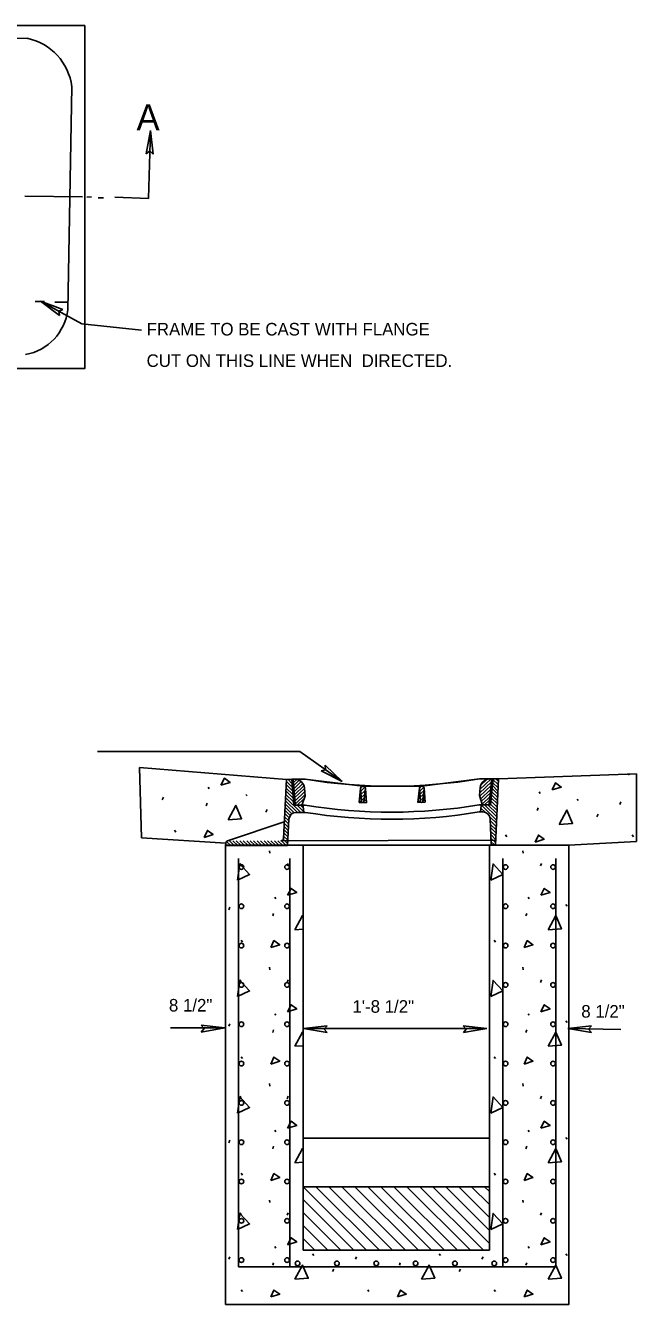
# Model space of a CAD drawing. Extents: x 0.9 to 8.1, y 0.4 to 10.5.
# Drawn here: x 5.569 to 7.899, y 5.354 to 10.233 of the extents above; entities that cross this region are included whole.
import ezdxf

# ---------------------------------------------------------------- set-up
doc = ezdxf.new("R2010")
doc.units = 0
for name, color, linetype in [('DETL-DIMS', 7, 'Continuous'), ('DETL-LINE', 7, 'Continuous'), ('DETL-NOTE', 7, 'Continuous')]:
    doc.layers.add(name, color=color, linetype=linetype)

msp = doc.modelspace()

# ---------------------------------------------------------------- linework, layer by layer
at = {"layer": 'DETL-DIMS'}
for p, q in [((6.0293, 9.7442), (6.0452, 9.8337)), ((6.0372, 9.5743), (6.0452, 9.8337)), ((6.0556, 9.7433), (6.0452, 9.8337)), ((6.0293, 9.7442), (6.0428, 9.755)), ((6.0556, 9.7433), (6.0428, 9.755)), ((5.9096, 9.5783), (6.0372, 9.5743)), ((5.6988, 9.1267), (5.6262, 9.1815)), ((5.7114, 9.1497), (5.6262, 9.1815)), ((5.7114, 9.1497), (5.6952, 9.1436)), ((5.6988, 9.1267), (5.6952, 9.1436)), ((6.696, 7.3899), (6.7127, 7.3941)), ((6.696, 7.3899), (6.777, 7.3486)), ((6.7111, 7.4113), (6.777, 7.3486)), ((6.7111, 7.4113), (6.7127, 7.3941)), ((6.1222, 6.4089), (6.3284, 6.4089)), ((6.238, 6.4192), (6.3284, 6.4089)), ((6.238, 6.4192), (6.2497, 6.4065)), ((6.2389, 6.393), (6.3284, 6.4089)), ((6.2389, 6.393), (6.2497, 6.4065)), ((6.7199, 6.4172), (6.6295, 6.4068)), ((6.6295, 6.4068), (7.3286, 6.4068)), ((6.7191, 6.3909), (6.6295, 6.4068)), ((6.7199, 6.4172), (6.7082, 6.4044)), ((6.7191, 6.3909), (6.7082, 6.4044)), ((7.2382, 6.4172), (7.3286, 6.4068)), ((7.2382, 6.4172), (7.2499, 6.4044)), ((7.2391, 6.3909), (7.3286, 6.4068)), ((7.2391, 6.3909), (7.2499, 6.4044)), ((7.7283, 6.4172), (7.6379, 6.4068)), ((7.6379, 6.4068), (7.84, 6.4027)), ((7.7275, 6.3909), (7.6379, 6.4068)), ((7.7283, 6.4172), (7.7167, 6.4044)), ((7.7275, 6.3909), (7.7167, 6.4044))]:
    msp.add_line(p, q, dxfattribs=at)
for points in [[(5.6262, 9.1815), (5.783, 9.0954), (6.0106, 9.0707)], [(6.777, 7.3486), (6.6151, 7.4633), (5.8426, 7.4642)]]:
    msp.add_lwpolyline(points, dxfattribs=at)
at = {"layer": 'DETL-LINE'}
for p, q in [((3.772, 10.1935), (5.5744, 10.1848)), ((5.7451, 10.0004), (5.7302, 9.1491)), ((5.6058, 9.1805), (5.6407, 9.1805)), ((5.6801, 9.1782), (5.7285, 9.1782)), ((6.5636, 7.3574), (6.0035, 7.4026)), ((6.0035, 7.4026), (6.0106, 7.1346)), ((7.3732, 7.3593), (7.8991, 7.3779)), ((7.873, 7.3769), (7.8693, 7.3752)), ((7.8693, 7.3752), (7.8695, 7.3768)), ((7.8991, 7.1205), (7.8991, 7.3779)), ((6.2658, 7.3277), (6.2694, 7.3217)), ((6.5527, 7.1319), (6.5636, 7.3574)), ((6.5621, 7.3253), (6.5894, 7.2988)), ((6.5627, 7.3376), (6.5883, 7.3128)), ((6.5633, 7.3499), (6.5871, 7.3267)), ((6.5636, 7.3574), (6.5847, 7.3575)), ((6.5688, 7.3575), (6.586, 7.3407)), ((6.582, 7.3575), (6.5849, 7.3546)), ((6.5847, 7.3575), (6.5926, 7.2584)), ((6.5847, 7.3575), (6.5894, 7.3575)), ((6.5894, 7.3575), (6.5969, 7.2625)), ((6.5894, 7.3575), (6.5961, 7.3575)), ((6.5895, 7.3566), (6.5904, 7.3575)), ((6.5904, 7.3448), (6.603, 7.3569)), ((6.5913, 7.3331), (6.6129, 7.3537)), ((6.5922, 7.3214), (6.6207, 7.3486)), ((6.5932, 7.3097), (6.6269, 7.3418)), ((6.5941, 7.298), (6.6312, 7.3334)), ((6.595, 7.2863), (6.6332, 7.3227)), ((6.5961, 7.3575), (6.6338, 7.3576)), ((6.633, 7.3247), (6.6354, 7.294)), ((6.8558, 7.3311), (6.6338, 7.3576)), ((6.8411, 7.2692), (6.8464, 7.3228)), ((6.8451, 7.3094), (6.8635, 7.3271)), ((6.8505, 7.2727), (6.8464, 7.3228)), ((6.8465, 7.3234), (6.8544, 7.331)), ((6.9681, 7.3313), (6.8558, 7.3311)), ((6.8598, 7.2728), (6.865, 7.3228)), ((6.8691, 7.268), (6.865, 7.3228)), ((6.9681, 7.3313), (7.0804, 7.3316)), ((7.0657, 7.2685), (7.071, 7.3233)), ((7.0697, 7.3096), (7.0883, 7.3274)), ((7.071, 7.3235), (7.0795, 7.3315)), ((7.0751, 7.2732), (7.071, 7.3233)), ((7.0804, 7.3316), (7.3007, 7.3591)), ((7.0844, 7.2732), (7.0897, 7.3233)), ((7.0938, 7.2697), (7.0897, 7.3233)), ((7.3031, 7.3262), (7.2999, 7.2955)), ((7.3408, 7.3592), (7.3007, 7.3591)), ((7.3009, 7.3046), (7.3463, 7.348)), ((7.301, 7.2921), (7.3449, 7.334)), ((7.3023, 7.3186), (7.3449, 7.3592)), ((7.304, 7.2824), (7.3435, 7.32)), ((7.3046, 7.3333), (7.3301, 7.3577)), ((7.3475, 7.3592), (7.3377, 7.2642)), ((7.3475, 7.3592), (7.3408, 7.3592)), ((7.3522, 7.3592), (7.342, 7.2601)), ((7.3522, 7.3592), (7.3475, 7.3592)), ((7.3483, 7.3219), (7.3704, 7.3005)), ((7.3495, 7.3336), (7.371, 7.3128)), ((7.3507, 7.3453), (7.3715, 7.3251)), ((7.3519, 7.357), (7.3721, 7.3374)), ((7.3732, 7.3593), (7.3522, 7.3592)), ((7.3732, 7.3593), (7.3609, 7.1057)), ((7.3629, 7.3592), (7.3727, 7.3497)), ((6.0895, 7.2794), (6.0943, 7.2891)), ((6.4095, 7.2999), (6.4144, 7.2939)), ((6.5597, 7.2761), (6.6057, 7.2314)), ((6.5603, 7.2884), (6.6189, 7.2314)), ((6.5609, 7.3007), (6.5916, 7.2709)), ((6.5615, 7.313), (6.5905, 7.2848)), ((6.596, 7.2746), (6.6341, 7.311)), ((6.5969, 7.2629), (6.635, 7.2992)), ((6.6055, 7.2584), (6.632, 7.2838)), ((6.6245, 7.2614), (6.6354, 7.294)), ((6.8423, 7.2816), (6.8664, 7.3046)), ((6.8424, 7.2691), (6.8673, 7.2928)), ((6.8437, 7.2955), (6.8655, 7.3164)), ((6.8551, 7.2686), (6.8681, 7.2811)), ((7.0663, 7.2685), (7.092, 7.293)), ((7.067, 7.2818), (7.0911, 7.3048)), ((7.0683, 7.2957), (7.0902, 7.3165)), ((7.0801, 7.2691), (7.0929, 7.2813)), ((7.3101, 7.2629), (7.2999, 7.2955)), ((7.3071, 7.2727), (7.342, 7.3061)), ((7.3101, 7.263), (7.3406, 7.2921)), ((7.3202, 7.26), (7.3392, 7.2781)), ((7.3435, 7.275), (7.368, 7.2513)), ((7.3447, 7.2867), (7.3686, 7.2636)), ((7.3459, 7.2984), (7.3692, 7.2759)), ((7.3471, 7.3102), (7.3698, 7.2882)), ((7.5287, 7.31), (7.5324, 7.304)), ((7.6725, 7.2822), (7.6773, 7.2762)), ((7.8355, 7.2617), (7.8403, 7.2714)), ((6.2574, 7.2565), (6.261, 7.2661)), ((6.4856, 7.2323), (6.4904, 7.242)), ((6.5573, 7.2269), (6.5745, 7.2102)), ((6.5579, 7.2392), (6.5785, 7.2192)), ((6.5585, 7.2515), (6.5849, 7.2258)), ((6.5591, 7.2638), (6.5938, 7.2301)), ((6.5926, 7.2584), (6.6235, 7.2585)), ((6.6015, 7.2584), (6.6201, 7.2585)), ((6.602, 7.2314), (6.6238, 7.2314)), ((6.6044, 7.2584), (6.6298, 7.2338)), ((6.6176, 7.2585), (6.6287, 7.2478)), ((6.6187, 7.2585), (6.6258, 7.2652)), ((6.6235, 7.2585), (6.6264, 7.2585)), ((6.6235, 7.2585), (6.635, 7.2585)), ((6.6238, 7.2314), (6.63, 7.2315)), ((6.6281, 7.2544), (6.63, 7.2315)), ((6.63, 7.2315), (6.6347, 7.2315)), ((6.8411, 7.2692), (6.8691, 7.268)), ((6.8678, 7.2681), (6.869, 7.2693)), ((7.0938, 7.2697), (7.0657, 7.2685)), ((7.304, 7.233), (7.2992, 7.233)), ((7.311, 7.26), (7.2995, 7.26)), ((7.3063, 7.2559), (7.304, 7.233)), ((7.3101, 7.233), (7.304, 7.233)), ((7.3043, 7.2358), (7.3072, 7.233)), ((7.3055, 7.2475), (7.3218, 7.2317)), ((7.3075, 7.2584), (7.3656, 7.2021)), ((7.311, 7.26), (7.3081, 7.26)), ((7.3132, 7.233), (7.3101, 7.233)), ((7.342, 7.2601), (7.311, 7.26)), ((7.333, 7.2601), (7.3145, 7.26)), ((7.3191, 7.26), (7.3662, 7.2144)), ((7.3324, 7.2601), (7.3668, 7.2267)), ((7.3335, 7.2601), (7.3377, 7.2642)), ((7.3423, 7.2633), (7.3674, 7.239)), ((7.5203, 7.2387), (7.5239, 7.2484)), ((7.7486, 7.2146), (7.7534, 7.2243)), ((6.5558, 7.1955), (6.3388, 7.1222)), ((6.5549, 7.1777), (6.5711, 7.1619)), ((6.5555, 7.19), (6.5718, 7.1741)), ((6.5561, 7.2023), (6.5726, 7.1863)), ((6.5567, 7.2146), (6.5733, 7.1985)), ((6.5678, 7.1052), (6.5737, 7.2055)), ((7.3396, 7.2144), (7.365, 7.1898)), ((7.3446, 7.1069), (7.341, 7.2073)), ((7.3412, 7.1999), (7.3644, 7.1775)), ((7.3417, 7.1866), (7.3638, 7.1652)), ((7.3422, 7.1732), (7.3632, 7.1528)), ((6.3323, 7.1134), (6.0106, 7.1346)), ((6.1366, 7.1635), (6.1414, 7.1562)), ((7.3615, 7.125), (6.5432, 7.1232)), ((6.552, 7.129), (6.5682, 7.1132)), ((6.5531, 7.1408), (6.569, 7.1254)), ((6.5537, 7.1531), (6.5697, 7.1376)), ((6.5543, 7.1654), (6.5704, 7.1497)), ((7.3427, 7.1599), (7.3626, 7.1405)), ((7.3431, 7.1465), (7.362, 7.1282)), ((7.3436, 7.1332), (7.3614, 7.1159)), ((7.3995, 7.1458), (7.4044, 7.1385)), ((7.8826, 7.1458), (7.8874, 7.1385)), ((6.3314, 7.1047), (6.3324, 7.1145)), ((6.5678, 7.1052), (6.3314, 7.1047)), ((6.3321, 7.1106), (6.3382, 7.1047)), ((6.3355, 7.1202), (6.3514, 7.1047)), ((6.3462, 7.1227), (6.3647, 7.1047)), ((6.3594, 7.1227), (6.3779, 7.1048)), ((6.3726, 7.1228), (6.3911, 7.1048)), ((6.3859, 7.1228), (6.4044, 7.1048)), ((6.3991, 7.1228), (6.4176, 7.1049)), ((6.4123, 7.1229), (6.4309, 7.1049)), ((6.4256, 7.1229), (6.4441, 7.1049)), ((6.4388, 7.1229), (6.4573, 7.1049)), ((6.452, 7.123), (6.4706, 7.105)), ((6.4653, 7.123), (6.4838, 7.105)), ((6.4785, 7.123), (6.497, 7.105)), ((6.4918, 7.123), (6.5103, 7.1051)), ((6.4995, 7.0852), (6.5007, 7.0756)), ((6.505, 7.1231), (6.5235, 7.1051)), ((6.5182, 7.1231), (6.5367, 7.1051)), ((6.5315, 7.1231), (6.55, 7.1052)), ((6.5445, 7.1233), (6.5632, 7.1052)), ((7.3446, 7.1069), (6.5678, 7.1052)), ((6.6272, 7.1053), (6.6272, 5.5604)), ((7.3389, 7.1057), (7.3389, 5.5604)), ((7.3441, 7.1198), (7.3574, 7.107)), ((7.3609, 7.107), (7.3446, 7.1069)), ((7.4657, 7.0852), (7.4669, 7.0756)), ((7.8991, 7.1205), (7.6419, 7.1057)), ((6.3814, 5.4978), (6.3814, 7.0556)), ((6.3914, 7.0273), (6.3877, 7.0369)), ((6.5672, 7.0273), (6.5708, 7.0369)), ((6.5772, 5.4978), (6.5772, 7.0556)), ((7.3889, 7.0556), (7.3889, 5.4978)), ((7.5333, 7.0273), (7.537, 7.0369)), ((7.5919, 7.0556), (7.5919, 5.4978)), ((6.5201, 6.9077), (6.5237, 6.9017)), ((7.4862, 6.9077), (7.4899, 6.9017)), ((6.3437, 6.8594), (6.3486, 6.8691)), ((6.5116, 6.8364), (6.5152, 6.8461)), ((7.4778, 6.8364), (7.4814, 6.8461)), ((7.6299, 6.8799), (7.6348, 6.8739)), ((6.6272, 6.7855), (6.5961, 6.7833)), ((6.3908, 6.7435), (6.3957, 6.7362)), ((7.357, 6.7435), (7.3618, 6.7362)), ((6.4995, 6.6408), (6.5007, 6.6311)), ((7.4657, 6.6408), (7.4669, 6.6311)), ((6.3914, 6.5828), (6.3877, 6.5925)), ((6.5672, 6.5828), (6.5708, 6.5925)), ((7.5333, 6.5828), (7.537, 6.5925)), ((6.5201, 6.4633), (6.5237, 6.4572)), ((7.4862, 6.4633), (7.4899, 6.4572)), ((6.3437, 6.415), (6.3486, 6.4246)), ((6.5116, 6.392), (6.5152, 6.4017)), ((7.4778, 6.392), (7.4814, 6.4017)), ((7.6299, 6.4355), (7.6348, 6.4294)), ((6.3908, 6.299), (6.3957, 6.2918)), ((6.6272, 6.3411), (6.5961, 6.3389)), ((7.357, 6.299), (7.3618, 6.2918)), ((6.4995, 6.1964), (6.5007, 6.1867)), ((7.4657, 6.1964), (7.4669, 6.1867)), ((6.3914, 6.1384), (6.3877, 6.148)), ((6.5672, 6.1384), (6.5708, 6.148)), ((7.5333, 6.1384), (7.537, 6.148)), ((6.5201, 6.0188), (6.5237, 6.0128)), ((7.4862, 6.0188), (7.4899, 6.0128)), ((6.3437, 5.9705), (6.3486, 5.9802)), ((6.5116, 5.9476), (6.5152, 5.9572)), ((6.6272, 5.9888), (7.3389, 5.9888)), ((7.4778, 5.9476), (7.4814, 5.9572)), ((7.6299, 5.991), (7.6348, 5.985)), ((6.6272, 5.8966), (6.5961, 5.8944)), ((6.3908, 5.8546), (6.3957, 5.8473)), ((7.357, 5.8546), (7.3618, 5.8473)), ((7.3389, 5.8032), (6.6272, 5.8032)), ((6.6272, 5.8032), (6.87, 5.5604)), ((6.6767, 5.8032), (6.9195, 5.5604)), ((6.7262, 5.8032), (6.969, 5.5604)), ((6.7757, 5.8032), (7.0185, 5.5604)), ((6.8251, 5.8032), (7.068, 5.5604)), ((6.8746, 5.8032), (7.1175, 5.5604)), ((6.9241, 5.8032), (7.167, 5.5604)), ((6.9736, 5.8032), (7.2164, 5.5604)), ((7.0231, 5.8032), (7.2659, 5.5604)), ((7.0726, 5.8032), (7.3154, 5.5604)), ((7.1221, 5.8032), (7.3389, 5.5864)), ((7.1716, 5.8032), (7.3389, 5.6359)), ((7.2211, 5.8032), (7.3389, 5.6854)), ((7.2706, 5.8032), (7.3389, 5.7349)), ((7.3201, 5.8032), (7.3389, 5.7844)), ((6.4995, 5.7519), (6.5007, 5.7423)), ((6.6272, 5.7537), (6.8205, 5.5604)), ((7.4657, 5.7519), (7.4669, 5.7423)), ((6.3914, 5.6939), (6.3877, 5.7036)), ((6.5672, 5.6939), (6.5708, 5.7036)), ((6.6272, 5.7042), (6.771, 5.5604)), ((7.5333, 5.6939), (7.537, 5.7036)), ((6.6272, 5.6547), (6.7215, 5.5604)), ((6.5201, 5.5744), (6.5237, 5.5683)), ((6.6272, 5.6052), (6.672, 5.5604)), ((7.4862, 5.5744), (7.4899, 5.5683)), ((6.3437, 5.5261), (6.3486, 5.5357)), ((6.6272, 5.5604), (7.3389, 5.5604)), ((6.6638, 5.5466), (6.6686, 5.5406)), ((6.8268, 5.5261), (6.8316, 5.5357)), ((7.1469, 5.5466), (7.1517, 5.5406)), ((7.3099, 5.5261), (7.3147, 5.5357)), ((7.6299, 5.5466), (7.6348, 5.5406)), ((6.5772, 5.4978), (6.3814, 5.4978)), ((6.5116, 5.5031), (6.5152, 5.5128)), ((7.3889, 5.4978), (6.5772, 5.4978)), ((6.7399, 5.479), (6.7447, 5.4886)), ((6.9947, 5.5031), (6.9983, 5.5128)), ((7.2229, 5.479), (7.2278, 5.4886)), ((7.5919, 5.4978), (7.3889, 5.4978)), ((7.4778, 5.5031), (7.4814, 5.5128)), ((6.3908, 5.4101), (6.3957, 5.4029)), ((6.8739, 5.4101), (6.8787, 5.4029)), ((7.357, 5.4101), (7.3618, 5.4029))]:
    msp.add_line(p, q, dxfattribs=at)
for points in [[(3.5539, 10.2335), (5.7946, 10.2335), (5.7946, 8.9249), (3.5539, 8.9249)], [(6.3314, 5.3539), (7.6419, 5.3539), (7.6419, 7.1057), (6.3314, 7.1057)]]:
    msp.add_lwpolyline(points, close=True, dxfattribs=at)
for points in [[(6.3141, 7.335), (6.3274, 7.3615), (6.3491, 7.3458), (6.3141, 7.335)], [(7.5771, 7.3172), (7.5903, 7.3438), (7.6121, 7.3281), (7.5771, 7.3172)], [(6.3419, 7.2033), (6.3709, 7.2577), (6.3926, 7.2069), (6.3419, 7.2033)], [(7.6048, 7.1856), (7.6338, 7.24), (7.6556, 7.1892), (7.6048, 7.1856)], [(6.2501, 7.1357), (6.2622, 7.1623), (6.2839, 7.1466), (6.2501, 7.1357)], [(7.513, 7.118), (7.5251, 7.1445), (7.5469, 7.1288), (7.513, 7.118)], [(6.3775, 6.9729), (6.386, 7.0345), (6.4234, 6.9947), (6.3775, 6.9729)], [(7.3437, 6.9729), (7.3522, 7.0345), (7.3896, 6.9947), (7.3437, 6.9729)], [(6.5684, 6.915), (6.5816, 6.9415), (6.6034, 6.9258), (6.5684, 6.915)], [(7.5345, 6.915), (7.5478, 6.9415), (7.5696, 6.9258), (7.5345, 6.915)], [(6.5961, 6.7833), (6.6251, 6.8377), (6.6272, 6.8329)], [(7.5623, 6.7833), (7.5913, 6.8377), (7.613, 6.7869), (7.5623, 6.7833)], [(6.5044, 6.7157), (6.5164, 6.7422), (6.5382, 6.7265), (6.5044, 6.7157)], [(7.4705, 6.7157), (7.4826, 6.7422), (7.5043, 6.7265), (7.4705, 6.7157)], [(6.3775, 6.5285), (6.386, 6.5901), (6.4234, 6.5502), (6.3775, 6.5285)], [(7.3437, 6.5285), (7.3522, 6.5901), (7.3896, 6.5502), (7.3437, 6.5285)], [(6.5684, 6.4705), (6.5816, 6.4971), (6.6034, 6.4814), (6.5684, 6.4705)], [(7.5345, 6.4705), (7.5478, 6.4971), (7.5696, 6.4814), (7.5345, 6.4705)], [(6.5961, 6.3389), (6.6251, 6.3932), (6.6272, 6.3885)], [(7.5623, 6.3389), (7.5913, 6.3932), (7.613, 6.3425), (7.5623, 6.3389)], [(6.5044, 6.2712), (6.5164, 6.2978), (6.5382, 6.2821), (6.5044, 6.2712)], [(7.4705, 6.2712), (7.4826, 6.2978), (7.5043, 6.2821), (7.4705, 6.2712)], [(6.3775, 6.084), (6.386, 6.1456), (6.4234, 6.1058), (6.3775, 6.084)], [(7.3437, 6.084), (7.3522, 6.1456), (7.3896, 6.1058), (7.3437, 6.084)], [(6.5684, 6.0261), (6.5816, 6.0526), (6.6034, 6.0369), (6.5684, 6.0261)], [(7.5345, 6.0261), (7.5478, 6.0526), (7.5696, 6.0369), (7.5345, 6.0261)], [(6.5961, 5.8944), (6.6251, 5.9488), (6.6272, 5.944)], [(7.5623, 5.8944), (7.5913, 5.9488), (7.613, 5.8981), (7.5623, 5.8944)], [(6.5044, 5.8268), (6.5164, 5.8534), (6.5382, 5.8377), (6.5044, 5.8268)], [(7.4705, 5.8268), (7.4826, 5.8534), (7.5043, 5.8377), (7.4705, 5.8268)], [(6.3775, 5.6396), (6.386, 5.7012), (6.4234, 5.6613), (6.3775, 5.6396)], [(7.3437, 5.6396), (7.3522, 5.7012), (7.3896, 5.6613), (7.3437, 5.6396)], [(6.5684, 5.5816), (6.5816, 5.6082), (6.6034, 5.5925), (6.5684, 5.5816)], [(7.5345, 5.5816), (7.5478, 5.6082), (7.5696, 5.5925), (7.5345, 5.5816)], [(6.5961, 5.45), (6.6251, 5.5043), (6.6469, 5.4536), (6.5961, 5.45)], [(7.0792, 5.45), (7.1082, 5.5043), (7.13, 5.4536), (7.0792, 5.45)], [(7.5623, 5.45), (7.5913, 5.5043), (7.613, 5.4536), (7.5623, 5.45)], [(6.5044, 5.3824), (6.5164, 5.4089), (6.5382, 5.3932), (6.5044, 5.3824)], [(6.9874, 5.3824), (6.9995, 5.4089), (7.0213, 5.3932), (6.9874, 5.3824)], [(7.4705, 5.3824), (7.4826, 5.4089), (7.5043, 5.3932), (7.4705, 5.3824)]]:
    msp.add_lwpolyline(points, dxfattribs=at)
for centre in [(6.3922, 7.0229), (6.5663, 7.0229), (7.3998, 7.0229), (7.581, 7.0229), (6.3922, 6.8729), (6.5663, 6.8729), (7.3998, 6.8729), (7.581, 6.8729), (6.3922, 6.7229), (6.5663, 6.7229), (7.3998, 6.7229), (7.581, 6.7229), (6.3922, 6.5729), (6.5663, 6.5729), (7.3998, 6.5729), (7.581, 6.5729), (6.3922, 6.4229), (6.5663, 6.4229), (7.3998, 6.4229), (7.581, 6.4229), (6.3922, 6.2729), (6.5663, 6.2729), (7.3998, 6.2729), (7.581, 6.2729), (6.3922, 6.1229), (6.5663, 6.1229), (7.3998, 6.1229), (7.581, 6.1229), (6.3922, 5.9729), (6.5663, 5.9729), (7.3998, 5.9729), (7.581, 5.9729), (6.3922, 5.8229), (6.5663, 5.8229), (7.3998, 5.8229), (7.581, 5.8229), (6.3922, 5.6729), (6.5663, 5.6729), (7.3998, 5.6729), (7.581, 5.6729), (6.3922, 5.5229), (6.5663, 5.5229), (6.6067, 5.5104), (6.7567, 5.5104), (6.9067, 5.5104), (7.0567, 5.5104), (7.2067, 5.5104), (7.3567, 5.5104), (7.3998, 5.5229), (7.581, 5.5229)]:
    msp.add_circle(centre, 0.00888, dxfattribs=at)
for centre, radius, start, end in [((5.532, 9.9743), 0.2148, 6.9634, 78.6055), ((5.5321, 9.1744), 0.1997, 280.5708, 352.7031)]:
    msp.add_arc(centre, radius, start, end, dxfattribs=at)
for centre, major_axis, start_param, end_param in [((6.5957, 7.3215), (0.0369, 0.0063), 6.196634, 7.680164), ((6.9901, 9.2372), (1.9538, 0.334), 4.369958, 4.707185), ((6.8557, 7.3221), (0.00924, 0.00158), 6.191943, 9.166524), ((7.0803, 7.3226), (0.00924, 0.00158), 6.193804, 9.168385), ((7.3403, 7.3231), (0.0369, 0.0063), 1.396979, 2.880509), ((6.8551, 7.2731), (0.00462, 0.00079), 3.052211, 6.026792), ((7.0798, 7.2736), (0.00462, 0.00079), 3.05035, 6.024932), ((6.6017, 7.2044), (0.0277, 0.0047), 1.396979, 2.922107), ((6.6016, 7.2629), (0.00462, 0.00079), 3.055042, 4.538571), ((6.6202, 7.263), (0.00462, 0.00079), 4.538571, 5.745573), ((6.6235, 7.254), (0.00462, 0.00079), 6.196634, 7.680164), ((6.9887, 9.111), (1.9538, 0.334), 4.369958, 4.707185), ((6.989, 9.1381), (1.9538, 0.334), 4.369958, 4.707185), ((7.311, 7.2555), (0.00462, 0.00079), 1.396979, 2.880509), ((7.3145, 7.2645), (0.00462, 0.00079), 3.33157, 4.538571), ((7.3129, 7.206), (0.0277, 0.0047), 6.155036, 7.680164), ((7.3331, 7.2646), (0.00462, 0.00079), 4.538571, 6.022101), ((6.5433, 7.1322), (0.00924, 0.00158), 4.538571, 6.073669), ((6.3418, 7.1137), (0.00924, 0.00158), 1.732505, 2.880509)]:
    msp.add_ellipse(centre, major_axis=major_axis, ratio=0.960366, start_param=start_param, end_param=end_param, dxfattribs=at)
at = {"layer": 'DETL-NOTE'}
for p, q in [((5.5665, 9.5823), (5.7859, 9.5803)), ((5.8019, 9.5783), (5.8198, 9.5803)), ((5.8458, 9.5763), (5.8657, 9.5763))]:
    msp.add_line(p, q, dxfattribs=at)

# ---------------------------------------------------------------- texts
for s, height, p in [('A', 0.099, (5.992, 9.8339)), ('FRAME TO BE CAST WITH FLANGE', 0.048, (6.0305, 9.051)), ('CUT ON THIS LINE WHEN  DIRECTED.', 0.048, (6.0305, 8.931)), ('8 1/2"', 0.048, (6.1157, 6.4715)), ('1\'-8 1/2"', 0.048, (6.8159, 6.4668)), ('8 1/2"', 0.048, (7.6888, 6.4482))]:
    msp.add_text(s, height=height, dxfattribs=at).set_placement(p)

doc.saveas('drawing.dxf')
